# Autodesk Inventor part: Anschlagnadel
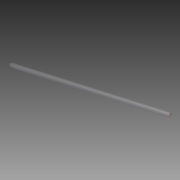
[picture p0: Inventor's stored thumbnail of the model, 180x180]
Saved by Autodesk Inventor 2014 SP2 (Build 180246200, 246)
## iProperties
Created: 2015-04
Part Number: Anschlagnadel
Material: Generisch
Document SubType Name: Modeling
Designer: e_krauts
Density: 1 g/cm^3
Appearance: Vorgabe
Author: e_krauts
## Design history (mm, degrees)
sketch "Skizze2"
  geometry: L1 (0, 0)-(0, -167.25); L2 (0, 0)-(3, 0); L3 (3, 0)-(3, -200); L4 (3, -200)-(1.66, -205); L5 (1.66, -205)-(0, -205)
  constraints: 10 end point, 3 perpendicular, 1 point on line, 1 vertical
  dimensions: "d3" = 6 diameter of L3 L1; "d4" = 15 deg angle of L3 L4; "d5" = 5 distance from line of L5 L3.end; "d6" = 205 distance between parallel lines of L2 L5
feature "Rotationsfläche1" sketch "Skizze2" dims angle "d7" = 90 deg
node "Volumenkörper1"
node "Fläche1"
